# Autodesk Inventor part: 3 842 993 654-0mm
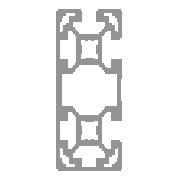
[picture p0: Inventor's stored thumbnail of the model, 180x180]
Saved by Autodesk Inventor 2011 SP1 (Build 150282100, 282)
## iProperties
Category: End -/-
Created: 2011-02
Part Number: 3 842 993 654-0mm
Document SubType Name: Modeling
Designer: SRW
Density: 2.71 g/cm^3
Categories: <MemberInstance><Categories><Category DisplayName="Structural Shapes" InternalName="089c4875-fa83-4c05-b084-43b9cc11f5ed" Mnemonic="GRDR"><CategoryParameter Dis
Stock Number: 3 842 993 654
Description: PROFILE 40x80 3SA, -/-
Material: Aluminum-6061
Mass: 69.891 g
Surface Area: 242.066 cm^2
Volume: 25.7901 cm^3
G_L: 25.000 mm
Author: SRW
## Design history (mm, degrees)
node "Blocks"
  sketch "40X80"
    geometry: L1 (26.765, 27.076)-(27.682, 26.676); L2 (37.765, 22.28)-(36.849, 22.68); L3 (27.682, 22.68)-(26.765, 22.28); L4 (26.765, 19.178)-(29.868, 19.178); L5 (26.765, 22.28)-(26.765, 19.178); L6 (29.868, 19.178)-(30.267, 20.095); L7 (34.264, 20.095)-(34.663, 19.178); L8 (34.663, 19.178)-(37.765, 19.178); L9 (37.765, 19.178)-(37.765, 22.28); L10 (36.849, 26.676)-(37.765, 27.076); L11 (43.73, 14.628)-(39.765, 18.592); L12 (46.265, 14.628)-(43.73, 14.628); L13 (46.265, 19.678)-(46.265, 14.628); L14 (50.765, 19.678)-(46.265, 19.678); L15 (50.765, 18.878)-(50.765, 19.678); L16 (52.265, 18.878)-(50.765, 18.878); L17 (52.265, 7.787)-(52.265, 18.878); L18 (27.265, 6.287)-(37.265, 6.287); L19 (37.265, 10.787)-(37.265, 6.287); L20 (42.315, 10.787)-(37.265, 10.787); L21 (42.315, 13.322)-(42.315, 10.787); L22 (38.351, 17.287)-(42.315, 13.322); L23 (47.765, 15.178)-(47.765, 12.928); L24 (47.765, 12.928)-(46.765, 12.928); L25 (44.015, 9.178)-(41.765, 9.178); L26 (44.015, 10.178)-(44.015, 9.178); L27 (41.765, 6.178)-(46.765, 6.178); L28 (46.765, 6.178)-(46.765, 7.428); L29 (49.515, 10.178)-(50.765, 10.178); L30 (50.765, 10.178)-(50.765, 15.178); L31 (12.265, 18.878)-(12.265, 7.787); L32 (18.265, 19.678)-(13.765, 19.678); L33 (18.265, 14.628)-(18.265, 19.678); L34 (20.801, 14.628)-(18.265, 14.628); L35 (24.765, 18.592)-(20.801, 14.628); L36 (22.215, 13.322)-(26.18, 17.287); L37 (22.215, 10.787)-(22.215, 13.322); L38 (27.265, 10.787)-(22.215, 10.787); L39 (27.265, 6.287)-(27.265, 10.787); L40 (15.265, 4.787)-(49.265, 4.787); L41 (20.515, 9.178)-(20.515, 10.178); L42 (22.765, 9.178)-(20.515, 9.178); L43 (16.765, 12.928)-(16.765, 15.178); L44 (17.765, 12.928)-(16.765, 12.928); L45 (13.765, 15.178)-(13.765, 10.178); L46 (13.765, 10.178)-(15.015, 10.178); L47 (17.765, 6.178)-(22.765, 6.178); L48 (17.765, 7.428)-(17.765, 6.178); L49 (46.765, 82.145)-(46.765, 83.395); L50 (20.801, 74.945)-(24.765, 70.981); L51 (18.265, 74.945)-(20.801, 74.945); L52 (18.265, 69.895)-(18.265, 74.945); L53 (13.765, 69.895)-(18.265, 69.895); L54 (12.265, 81.787)-(12.265, 18.878); L55 (26.465, 84.787)-(15.265, 84.787); L56 (26.465, 83.287)-(26.465, 84.787); L57 (27.265, 83.287)-(26.465, 83.287); L58 (27.265, 78.787)-(27.265, 83.287); L59 (22.215, 78.787)-(27.265, 78.787); L60 (22.215, 76.251)-(22.215, 78.787); L61 (26.18, 72.287)-(22.215, 76.251); L62 (20.515, 80.395)-(22.765, 80.395); L63 (20.515, 79.395)-(20.515, 80.395); L64 (16.765, 74.395)-(16.765, 76.645)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; A1 r 5 centre (32.265, 24.678) between (36.849, 22.68) and (36.849, 26.676); A2 r 5 centre (32.265, 24.678) between (27.682, 26.676) and (27.682, 22.68); A3 r 5 centre (32.265, 24.678) between (30.267, 20.095) and (34.264, 20.095); A4 r 3 centre (49.265, 7.787) between (49.265, 4.787) and (52.265, 7.787); A5 r 1.5 centre (49.265, 15.178) between (50.765, 15.178) and (47.765, 15.178); A6 r 1.5 centre (41.765, 7.678) between (41.765, 9.178) and (41.765, 6.178); A7 r 2.75 centre (46.765, 10.178) between (46.765, 12.928) and (44.015, 10.178); A8 r 2.75 centre (46.765, 10.178) between (46.765, 7.428) and (49.515, 10.178); A9 r 3 centre (15.265, 7.787) between (12.265, 7.787) and (15.265, 4.787); A10 r 1.5 centre (15.265, 15.178) between (16.765, 15.178) and (13.765, 15.178); A11 r 2.75 centre (17.765, 10.178) between (20.515, 10.178) and (17.765, 12.928); A12 r 2.75 centre (17.765, 10.178) between (15.015, 10.178) and (17.765, 7.428); A13 r 1.5 centre (22.765, 7.678) between (22.765, 6.178) and (22.765, 9.178); A14 r 3 centre (15.265, 81.787) between (15.265, 84.787) and (12.265, 81.787); A15 r 1.5 centre (22.765, 81.895) between (22.765, 80.395) and (22.765, 83.395); A16 r 2.75 centre (17.765, 79.395) between (17.765, 76.645) and (20.515, 79.395); A17 r 1.5 centre (15.265, 74.395) between (13.765, 74.395) and (16.765, 74.395); A18 r 2.75 centre (17.765, 79.395) between (17.765, 82.145) and (15.015, 79.395); A19 r 1.5 centre (41.765, 81.895) between (41.765, 83.395) and (41.765, 80.395); A20 r 2.75 centre (46.765, 79.395) between (49.515, 79.395) and (46.765, 82.145); A21 r 2.75 centre (46.765, 79.395) between (44.015, 79.395) and (46.765, 76.645); A22 r 1.5 centre (49.265, 74.395) between (47.765, 74.395) and (50.765, 74.395); A23 r 3 centre (49.265, 81.787) between (52.265, 81.787) and (49.265, 84.787); A24 r 5 centre (32.265, 64.895) between (34.264, 69.478) and (30.267, 69.478); A25 r 5 centre (32.265, 64.895) between (36.849, 62.897) and (36.849, 66.893); A26 r 5 centre (32.265, 64.895) between (30.267, 60.312) and (34.264, 60.312); A27 r 5 centre (32.265, 64.895) between (27.682, 66.893) and (27.682, 62.897); A28 r 5 centre (32.265, 24.678) between (34.264, 29.261) and (30.267, 29.261); 1 further point
    constraints: 314 end point, 56 point on circle, 28 centre point, 1 coincident
node "Start Plane"
node "End Plane"
sketch "Sketch1"
  geometry: 1 further point
  constraints: 1 other
extrude "Body" new body sketch "Sketch1" stored distance "d4" = 0.13; taper "d5" = 0 deg
node "Driven Length"
  sketch "Sketch51"
    geometry: L1 (0, 0)-(10, 0) reference
    constraints: 2 end point, 1 horizontal
  workplane "Work Plane22"
  sketch "Sketch52"
    geometry: L1 (-2, 0)-(12, 0) reference; L2 (-2, 25)-(12, 25) reference
    dimensions: "d7" = 25 distance between parallel lines of L1 L2 (derived)
sketch "Sketch9"
  geometry: 2 further points
  constraints: 1 vertical alignment
  dimensions: "d88" = 40 distance of point (0, 0) point (0, -40)
hole "M12/-" sketch "Sketch9" at (0, 0), (0, -40) diameter "d17" = 10.106; stored, may be unused: countersink angle "d21" = 90 deg, drill point angle "d23" = 118 deg; dims "d18" = 6, "d19" = 4, "d20" = 2, "d22" = 55
sketch "Sketch10"
  geometry: 2 further points
  constraints: 1 vertical alignment
  dimensions: "d89" = 40 distance of point (0, 0) point (0, -40)
hole "-/M12" sketch "Sketch10" at (0, 0), (0, -40) diameter "d24" = 10.106; stored, may be unused: countersink angle "d28" = 90 deg, drill point angle "d30" = 118 deg; dims "d25" = 6, "d26" = 4, "d27" = 2, "d29" = 55
sketch "Sketch11"
  geometry: L1 (-13.7, 0)-(12.2, 0) reference; C1 r 8.5 at (0, 20); 1 further point
  constraints: 1 centre point, 1 vertical alignment
  dimensions: "d31" = 20 distance from line of C1.centre L1; "d32" = 17 diameter of C1
extrude "D17VS/-" cut sketch "Sketch11" stored distance "d33" = 10; taper "d34" = 0 deg
sketch "Sketch12"
  geometry: L1 (-13.7, 25)-(12.2, 25) reference; C1 r 8.5 at (0, 5); 1 further point
  constraints: 1 centre point, 1 vertical alignment
  dimensions: "d35" = 17 diameter of C1; "d36" = 20 distance from line of L1 C1.centre
extrude "-/D17VS" cut sketch "Sketch12" stored distance "d37" = 10; taper "d38" = 0 deg
sketch "Sketch13"
  geometry: L1 (-12.98, 0)-(7.88, 0) reference; C1 r 4.9 at (0, 20); 1 further point
  constraints: 1 centre point, 1 vertical alignment
  dimensions: "d39" = 9.8 diameter of C1; "d40" = 20 distance from line of C1.centre L1
extrude "D9.8VS/-" cut sketch "Sketch13" stored distance "d41" = 10; taper "d42" = 0 deg
sketch "Sketch14"
  geometry: L1 (-12.98, 25)-(7.88, 25) reference; C1 r 4.9 at (0, 5); 1 further point
  constraints: 1 centre point, 1 vertical alignment
  dimensions: "d43" = 9.8 diameter of C1; "d44" = 20 distance from line of L1 C1.centre
extrude "-/D9.8VS" cut sketch "Sketch14" stored distance "d45" = 10; taper "d46" = 0 deg
sketch "Sketch15"
  geometry: L1 (-54.86, 25)-(14.86, 25) reference; C1 r 4.9 at (0, 5); C2 r 4.9 at (-40, 5); 1 further point
  constraints: 2 centre point, 1 equal radius, 1 horizontal alignment, 1 vertical alignment
  dimensions: "d47" = 9.8 diameter of C1; "d48" = 20 distance from line of L1 C1.centre; "d92" = 40 distance of C1.centre C2.centre
extrude "-/D9.8" cut sketch "Sketch15" stored distance "d49" = 10; taper "d50" = 0 deg
sketch "Sketch26"
  geometry: L1 (-54.86, 0)-(14.86, 0) reference; C1 r 4.9 at (0, 20); C2 r 4.9 at (-40, 20); 1 further point
  constraints: 2 centre point, 1 equal radius, 1 horizontal alignment, 1 vertical alignment
  dimensions: "d62" = 9.8 diameter of C1; "d65" = 20 distance from line of L1 C1.centre; "d93" = 40 distance of C1.centre C2.centre
extrude "D9.8/-" cut sketch "Sketch26" stored distance "d63" = 10; taper "d64" = 0 deg
sketch "Sketch37"
  geometry: L1 (-59.9, 0)-(19.9, 0) reference; L2 (-59.9, 25)-(19.9, 25) reference; C1 r 8.5 at (0, 20); C2 r 8.5 at (-40, 20); 1 further point
  constraints: 2 centre point, 1 equal radius, 1 horizontal alignment, 1 vertical alignment
  dimensions: "d76" = 20 distance from line of C1.centre L1; "d77" = 17 diameter of C1; "d90" = 40 distance of C1.centre C2.centre
extrude "D17/-" cut sketch "Sketch37" stored distance "d78" = 10; taper "d79" = 0 deg
sketch "Sketch38"
  geometry: L1 (-59.9, 25)-(19.9, 25) reference; C1 r 8.5 at (0, 5); C2 r 8.5 at (-40, 5); 1 further point
  constraints: 2 centre point, 1 equal radius, 1 horizontal alignment, 1 vertical alignment
  dimensions: "d80" = 17 diameter of C1; "d81" = 20 distance from line of L1 C1.centre; "d91" = 40 distance of C1.centre C2.centre
extrude "-/D17" cut sketch "Sketch38" stored distance "d82" = 10; taper "d83" = 0 deg
body "Solid1"
node "40X80:1"
other parameters: "Length" = 25, "G_OFFSET_START" = 0 [user parameter; used in 2 equation terms], "G_OFFSET_END" = 0 [user parameter; used in 2 equation terms], "d2" = 0 (computed from G_OFFSET_START), "d3" = 25 (= Length + G_OFFSET_END), "G_L" = 25 (= d7) [user parameter], "Length2" = 25 (= G_OFFSET_START + Length + G_OFFSET_END) [user parameter], "d102" = 90 deg
